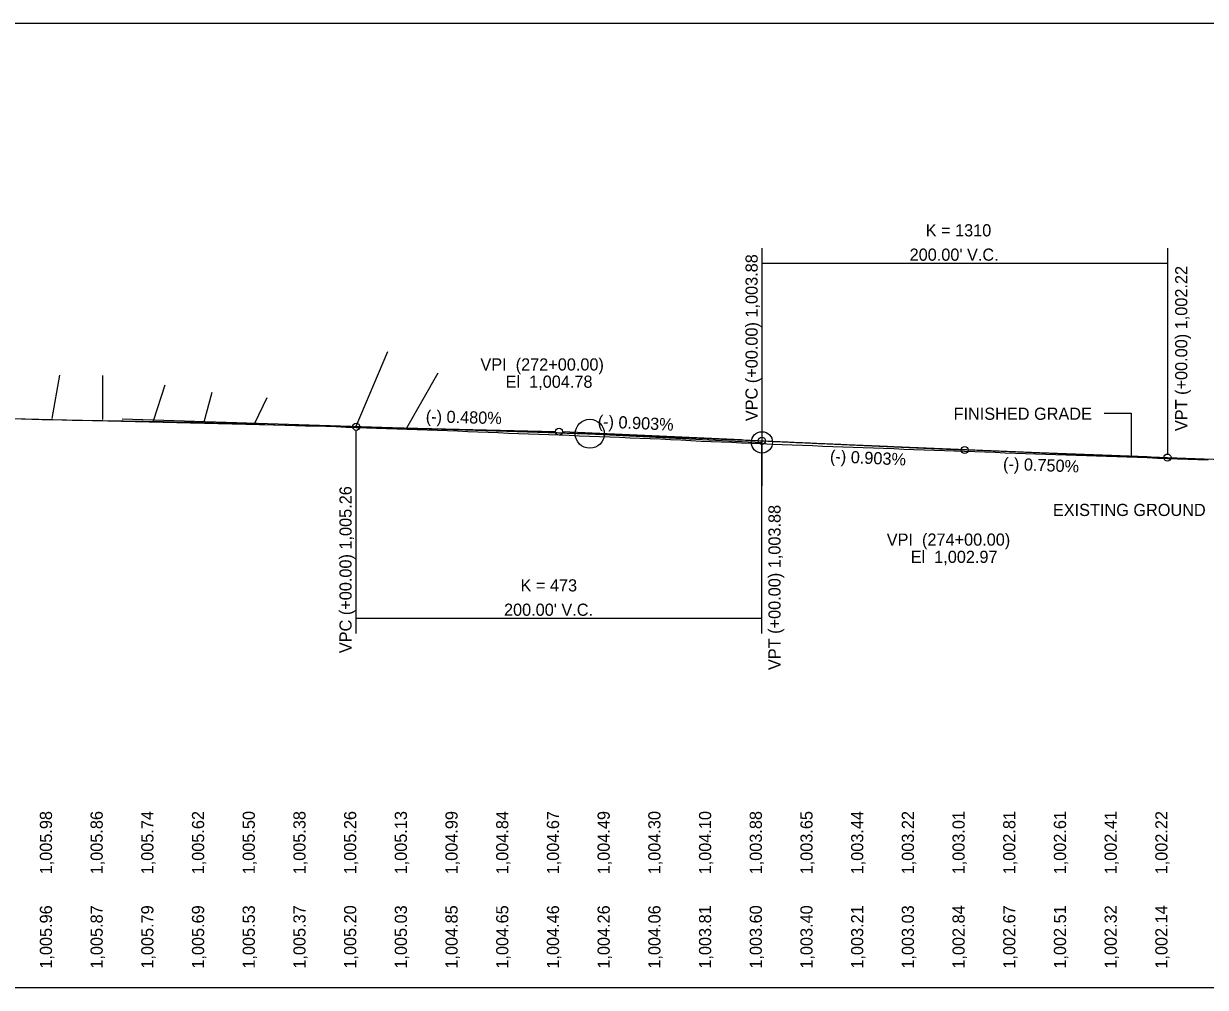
# Model space of a CAD drawing. Extents: x 4180 to 16997695, y 4 to 12629821.
# Drawn here: x 16979356 to 16979939, y 12628962 to 12629437 of the extents above; entities that cross this region are included whole.
import ezdxf

# ---------------------------------------------------------------- set-up
doc = ezdxf.new("R2010")
doc.units = 0
for name, color, linetype in [('Default', 7, 'Continuous'), ('RD_DDB_EX_Tx', 7, 'Continuous'), ('RD_DDB_GradeTX', 7, 'Continuous'), ('RD_DDB_PI', 7, 'Continuous'), ('RD_DDB_PR_Tx', 7, 'Continuous'), ('RD_DDB_Profile_EX', 7, 'Continuous'), ('RD_DDB_Profile_PR', 7, 'Continuous'), ('RD_DDB_StripGrade', 7, 'Continuous'), ('RD_DDB_StripGrade_PR', 7, 'Continuous'), ('RD_DDB_VCLbl', 7, 'Continuous'), ('RD_Sketch10', 7, 'Continuous')]:
    doc.layers.add(name, color=color, linetype=linetype)

msp = doc.modelspace()

# ---------------------------------------------------------------- linework, layer by layer
at = {"layer": 'Default'}
for p, q in [((16979404.53, 12629241.85), (16979635.03, 12629234.48)), ((16979635.03, 12629234.48), (16979719.88, 12629230.24))]:
    msp.add_line(p, q, dxfattribs=at)
msp.add_lwpolyline([(16979219.88, 12628961.61), (16980719.88, 12628961.61), (16980719.88, 12629436.61), (16979219.88, 12629436.61)], close=True, dxfattribs=at)
at = {"layer": 'RD_DDB_PI'}
for p, q in [((16979529.9, 12629237.67), (16979618.13, 12629235.55)), ((16979709.78, 12629231.45), (16979621.62, 12629235.43)), ((16979729.97, 12629230.54), (16979818.13, 12629226.56)), ((16979909.81, 12629223.11), (16979821.62, 12629226.42))]:
    msp.add_line(p, q, dxfattribs=at)
for centre in [(16979619.88, 12629235.51), (16979819.88, 12629226.49)]:
    msp.add_circle(centre, 1.75, dxfattribs=at)
at = {"layer": 'RD_DDB_PR_Tx'}
for p, q in [((16979888.59, 12629244.55), (16979902.01, 12629244.55)), ((16979902.01, 12629244.55), (16979902.01, 12629223.41))]:
    msp.add_line(p, q, dxfattribs=at)
at = {"layer": 'RD_DDB_Profile_EX'}
for points in [[(16979354.88, 12629241.83), (16979359.88, 12629241.7), (16979364.88, 12629241.56), (16979369.88, 12629241.43), (16979374.88, 12629241.33), (16979379.88, 12629241.22), (16979384.88, 12629241.12), (16979389.88, 12629241.04), (16979394.88, 12629240.97), (16979399.88, 12629240.9), (16979404.88, 12629240.82), (16979409.88, 12629240.75), (16979414.88, 12629240.67), (16979419.88, 12629240.58), (16979424.88, 12629240.47), (16979429.88, 12629240.36), (16979434.88, 12629240.25), (16979439.88, 12629240.15), (16979444.88, 12629240.04), (16979449.88, 12629239.91), (16979454.88, 12629239.77), (16979459.88, 12629239.62), (16979464.88, 12629239.46), (16979469.88, 12629239.29), (16979474.88, 12629239.11), (16979479.88, 12629238.93), (16979484.88, 12629238.76), (16979489.88, 12629238.58), (16979494.88, 12629238.45), (16979499.88, 12629238.33), (16979504.88, 12629238.2), (16979509.88, 12629238.01), (16979514.88, 12629237.8), (16979519.88, 12629237.59), (16979524.88, 12629237.39), (16979529.88, 12629237.22), (16979534.88, 12629237.06), (16979539.88, 12629236.92), (16979544.88, 12629236.78), (16979549.88, 12629236.62), (16979554.88, 12629236.45), (16979559.88, 12629236.27), (16979564.88, 12629236.06), (16979569.88, 12629235.86), (16979574.88, 12629235.65), (16979579.88, 12629235.44), (16979584.88, 12629235.24), (16979589.88, 12629235.04), (16979594.88, 12629234.84), (16979599.88, 12629234.65), (16979604.88, 12629234.45), (16979609.88, 12629234.26), (16979614.88, 12629234.07), (16979619.88, 12629233.89)], [(16979619.88, 12629233.89), (16979624.88, 12629233.7), (16979629.88, 12629233.52), (16979634.88, 12629233.32), (16979639.88, 12629233.12), (16979644.88, 12629232.91), (16979649.88, 12629232.73), (16979654.88, 12629232.54), (16979659.88, 12629232.36), (16979664.88, 12629232.16), (16979669.88, 12629231.94), (16979674.88, 12629231.7), (16979679.88, 12629231.44), (16979684.88, 12629231.16), (16979689.88, 12629230.89), (16979694.88, 12629230.68), (16979699.88, 12629230.49), (16979704.88, 12629230.26), (16979709.88, 12629230.04), (16979714.88, 12629229.82), (16979719.88, 12629229.61), (16979724.88, 12629229.4), (16979729.88, 12629229.19), (16979734.88, 12629228.99), (16979739.88, 12629228.8), (16979744.88, 12629228.61), (16979749.88, 12629228.42), (16979754.88, 12629228.24), (16979759.88, 12629228.05), (16979764.88, 12629227.87), (16979769.88, 12629227.68), (16979774.88, 12629227.49), (16979779.88, 12629227.31), (16979784.88, 12629227.13), (16979789.88, 12629226.95), (16979794.88, 12629226.77), (16979799.88, 12629226.57), (16979804.88, 12629226.37), (16979809.88, 12629226.17), (16979814.88, 12629226), (16979819.88, 12629225.84), (16979824.88, 12629225.67), (16979829.88, 12629225.5), (16979834.88, 12629225.32), (16979839.88, 12629225.14), (16979844.88, 12629224.97), (16979849.88, 12629224.81), (16979854.88, 12629224.65), (16979859.88, 12629224.49), (16979864.88, 12629224.32), (16979869.88, 12629224.15), (16979874.88, 12629223.98), (16979879.88, 12629223.81), (16979884.88, 12629223.61), (16979889.88, 12629223.4), (16979894.88, 12629223.22), (16979899.88, 12629223.05), (16979904.88, 12629222.89), (16979909.88, 12629222.72), (16979914.88, 12629222.52), (16979919.88, 12629222.33), (16979924.88, 12629222.13), (16979929.88, 12629221.94), (16979934.88, 12629221.78), (16979939.88, 12629221.61)]]:
    msp.add_lwpolyline(points, dxfattribs=at)
at = {"layer": 'RD_DDB_Profile_PR'}
for p, q in [((16979219.88, 12629245.11), (16979519.88, 12629237.91)), ((16979919.88, 12629222.74), (16980019.88, 12629218.99))]:
    msp.add_line(p, q, dxfattribs=at)
for points in [[(16979519.88, 12629237.91), (16979523.88, 12629237.81), (16979527.88, 12629237.72), (16979531.88, 12629237.62), (16979535.88, 12629237.51), (16979539.88, 12629237.41), (16979543.88, 12629237.31), (16979547.88, 12629237.2), (16979551.88, 12629237.09), (16979555.88, 12629236.98), (16979559.88, 12629236.87), (16979563.88, 12629236.75), (16979567.88, 12629236.64), (16979571.88, 12629236.52), (16979575.88, 12629236.4), (16979579.88, 12629236.28), (16979583.88, 12629236.16), (16979587.88, 12629236.04), (16979591.88, 12629235.91), (16979595.88, 12629235.78), (16979599.88, 12629235.65), (16979603.88, 12629235.52), (16979607.88, 12629235.39), (16979611.88, 12629235.26), (16979615.88, 12629235.12), (16979619.88, 12629234.98), (16979623.88, 12629234.84), (16979627.88, 12629234.7), (16979631.88, 12629234.56), (16979635.88, 12629234.42), (16979639.88, 12629234.27), (16979643.88, 12629234.12), (16979647.88, 12629233.97), (16979651.88, 12629233.82), (16979655.88, 12629233.67), (16979659.88, 12629233.52), (16979663.88, 12629233.36), (16979667.88, 12629233.2), (16979671.88, 12629233.04), (16979675.88, 12629232.88), (16979679.88, 12629232.72), (16979683.88, 12629232.55), (16979687.88, 12629232.39), (16979691.88, 12629232.22), (16979695.88, 12629232.05), (16979699.88, 12629231.88), (16979703.88, 12629231.71), (16979707.88, 12629231.53), (16979711.88, 12629231.36), (16979715.88, 12629231.18), (16979719.88, 12629231)], [(16979719.88, 12629231), (16979723.88, 12629230.82), (16979727.88, 12629230.64), (16979731.88, 12629230.46), (16979735.88, 12629230.28), (16979739.88, 12629230.1), (16979743.88, 12629229.93), (16979747.88, 12629229.75), (16979751.88, 12629229.57), (16979755.88, 12629229.4), (16979759.88, 12629229.22), (16979763.88, 12629229.05), (16979767.88, 12629228.88), (16979771.88, 12629228.7), (16979775.88, 12629228.53), (16979779.88, 12629228.36), (16979783.88, 12629228.19), (16979787.88, 12629228.02), (16979791.88, 12629227.85), (16979795.88, 12629227.68), (16979799.88, 12629227.51), (16979803.88, 12629227.34), (16979807.88, 12629227.17), (16979811.88, 12629227.01), (16979815.88, 12629226.84), (16979819.88, 12629226.68), (16979823.88, 12629226.51), (16979827.88, 12629226.35), (16979831.88, 12629226.18), (16979835.88, 12629226.02), (16979839.88, 12629225.86), (16979843.88, 12629225.7), (16979847.88, 12629225.53), (16979851.88, 12629225.37), (16979855.88, 12629225.21), (16979859.88, 12629225.05), (16979863.88, 12629224.9), (16979867.88, 12629224.74), (16979871.88, 12629224.58), (16979875.88, 12629224.42), (16979879.88, 12629224.27), (16979883.88, 12629224.11), (16979887.88, 12629223.95), (16979891.88, 12629223.8), (16979895.88, 12629223.65), (16979899.88, 12629223.49), (16979903.88, 12629223.34), (16979907.88, 12629223.19), (16979911.88, 12629223.04), (16979915.88, 12629222.89), (16979919.88, 12629222.74)]]:
    msp.add_spline(points, degree=3, dxfattribs=at)
at = {"layer": 'RD_DDB_VCLbl'}
for p, q in [((16979719.88, 12629326), (16979719.88, 12629232.75)), ((16979919.88, 12629326), (16979919.88, 12629224.49)), ((16979719.88, 12629318.5), (16979919.88, 12629318.5)), ((16979519.88, 12629136), (16979519.88, 12629236.16)), ((16979719.88, 12629136), (16979719.88, 12629229.25)), ((16979519.88, 12629143.5), (16979719.88, 12629143.5))]:
    msp.add_line(p, q, dxfattribs=at)
for centre in [(16979519.88, 12629237.91), (16979719.88, 12629231), (16979719.88, 12629231), (16979919.88, 12629222.74)]:
    msp.add_circle(centre, 1.75, dxfattribs=at)
at = {"layer": 'RD_Sketch10'}
for p, q in [((16979719.88, 12629293.76), (16979719.88, 12629208.8)), ((16979519.88, 12629238.16), (16979535.44, 12629275)), ((16979369.88, 12629242.06), (16979373.7, 12629263.43)), ((16979394.88, 12629241.51), (16979394.88, 12629263.22)), ((16979544.88, 12629237.36), (16979560.2, 12629264.52)), ((16979419.88, 12629240.91), (16979425.67, 12629258.57)), ((16979444.88, 12629240.31), (16979448.92, 12629254.97)), ((16979469.88, 12629239.66), (16979475.93, 12629252.28))]:
    msp.add_line(p, q, dxfattribs=at)
for centre, radius in [((16979635.03, 12629234.48), 7.17), ((16979719.88, 12629230.24), 5.26)]:
    msp.add_circle(centre, radius, dxfattribs=at)

# ---------------------------------------------------------------- texts
at = {"layer": 'RD_DDB_EX_Tx'}
msp.add_text('EXISTING GROUND', height=6, dxfattribs=at).set_placement((16979863.39, 12629193.93))
at = {"layer": 'RD_DDB_GradeTX'}
for s, rotation, p in [('(-) 0.480%', 358.62517, (16979554.11, 12629240.09)), ('(-) 0.903%', 357.41588, (16979638.84, 12629237.66)), ('(-) 0.903%', 357.41588, (16979753.38, 12629220.48)), ('(-) 0.750%', 357.85242, (16979838.73, 12629216.77))]:
    msp.add_text(s, height=6, rotation=rotation, dxfattribs=at).set_placement(p)
at = {"layer": 'RD_DDB_PI'}
for s, p in [('VPI  (272+00.00)', (16979581.11, 12629265.64)), ('El  1,004.78', (16979593.54, 12629257.14)), ('VPI  (274+00.00)', (16979781.46, 12629179.31)), ('El  1,002.97', (16979793.27, 12629170.81))]:
    msp.add_text(s, height=6, dxfattribs=at).set_placement(p)
at = {"layer": 'RD_DDB_PR_Tx'}
msp.add_text('FINISHED GRADE', height=6, dxfattribs=at).set_placement((16979814.41, 12629241.35))
at = {"layer": 'RD_DDB_StripGrade'}
for s, p in [('1,005.96', (16979369.88, 12628970.82)), ('1,005.87', (16979394.88, 12628970.82)), ('1,005.79', (16979419.88, 12628970.82)), ('1,005.69', (16979444.88, 12628970.82)), ('1,005.53', (16979469.88, 12628970.82)), ('1,005.37', (16979494.88, 12628970.82)), ('1,005.20', (16979519.88, 12628970.82)), ('1,005.03', (16979544.88, 12628970.82)), ('1,004.85', (16979569.88, 12628970.82)), ('1,004.65', (16979594.88, 12628970.82)), ('1,004.46', (16979619.88, 12628970.82)), ('1,004.26', (16979644.88, 12628970.82)), ('1,004.06', (16979669.88, 12628970.82)), ('1,003.81', (16979694.88, 12628970.82)), ('1,003.60', (16979719.88, 12628970.82)), ('1,003.40', (16979744.88, 12628970.82)), ('1,003.21', (16979769.88, 12628970.82)), ('1,003.03', (16979794.88, 12628970.82)), ('1,002.84', (16979819.88, 12628970.82)), ('1,002.67', (16979844.88, 12628970.82)), ('1,002.51', (16979869.88, 12628970.82)), ('1,002.32', (16979894.88, 12628970.82)), ('1,002.14', (16979919.88, 12628970.82))]:
    msp.add_text(s, height=6, rotation=90, dxfattribs=at).set_placement(p)
at = {"layer": 'RD_DDB_StripGrade_PR'}
for s, p in [('1,005.98', (16979369.88, 12629017.29)), ('1,005.86', (16979394.88, 12629017.29)), ('1,005.74', (16979419.88, 12629017.29)), ('1,005.62', (16979444.88, 12629017.29)), ('1,005.50', (16979469.88, 12629017.29)), ('1,005.38', (16979494.88, 12629017.29)), ('1,005.26', (16979519.88, 12629017.29)), ('1,005.13', (16979544.88, 12629017.29)), ('1,004.99', (16979569.88, 12629017.29)), ('1,004.84', (16979594.88, 12629017.29)), ('1,004.67', (16979619.88, 12629017.29)), ('1,004.49', (16979644.88, 12629017.29)), ('1,004.30', (16979669.88, 12629017.29)), ('1,004.10', (16979694.88, 12629017.29)), ('1,003.88', (16979719.88, 12629017.29)), ('1,003.65', (16979744.88, 12629017.29)), ('1,003.44', (16979769.88, 12629017.29)), ('1,003.22', (16979794.88, 12629017.29)), ('1,003.01', (16979819.88, 12629017.29)), ('1,002.81', (16979844.88, 12629017.29)), ('1,002.61', (16979869.88, 12629017.29)), ('1,002.41', (16979894.88, 12629017.29)), ('1,002.22', (16979919.88, 12629017.29))]:
    msp.add_text(s, height=6, rotation=90, dxfattribs=at).set_placement(p)
at = {"layer": 'RD_DDB_VCLbl'}
for s, p in [('K = 1310', (16979800.66, 12629331.75)), ("200.00' V.C.", (16979792.74, 12629319.75)), ('K = 473', (16979600.89, 12629156.75)), ("200.00' V.C.", (16979592.74, 12629144.75))]:
    msp.add_text(s, height=6, dxfattribs=at).set_placement(p)
for s, p in [('VPC (+00.00) 1,003.88', (16979717.82, 12629240.67)), ('VPT (+00.00) 1,002.22', (16979929.67, 12629235.78)), ('VPC (+00.00) 1,005.26', (16979517.61, 12629126.33)), ('VPT (+00.00) 1,003.88', (16979729.11, 12629118.01))]:
    msp.add_text(s, height=6, rotation=90, dxfattribs=at).set_placement(p)

doc.saveas('drawing.dxf')
